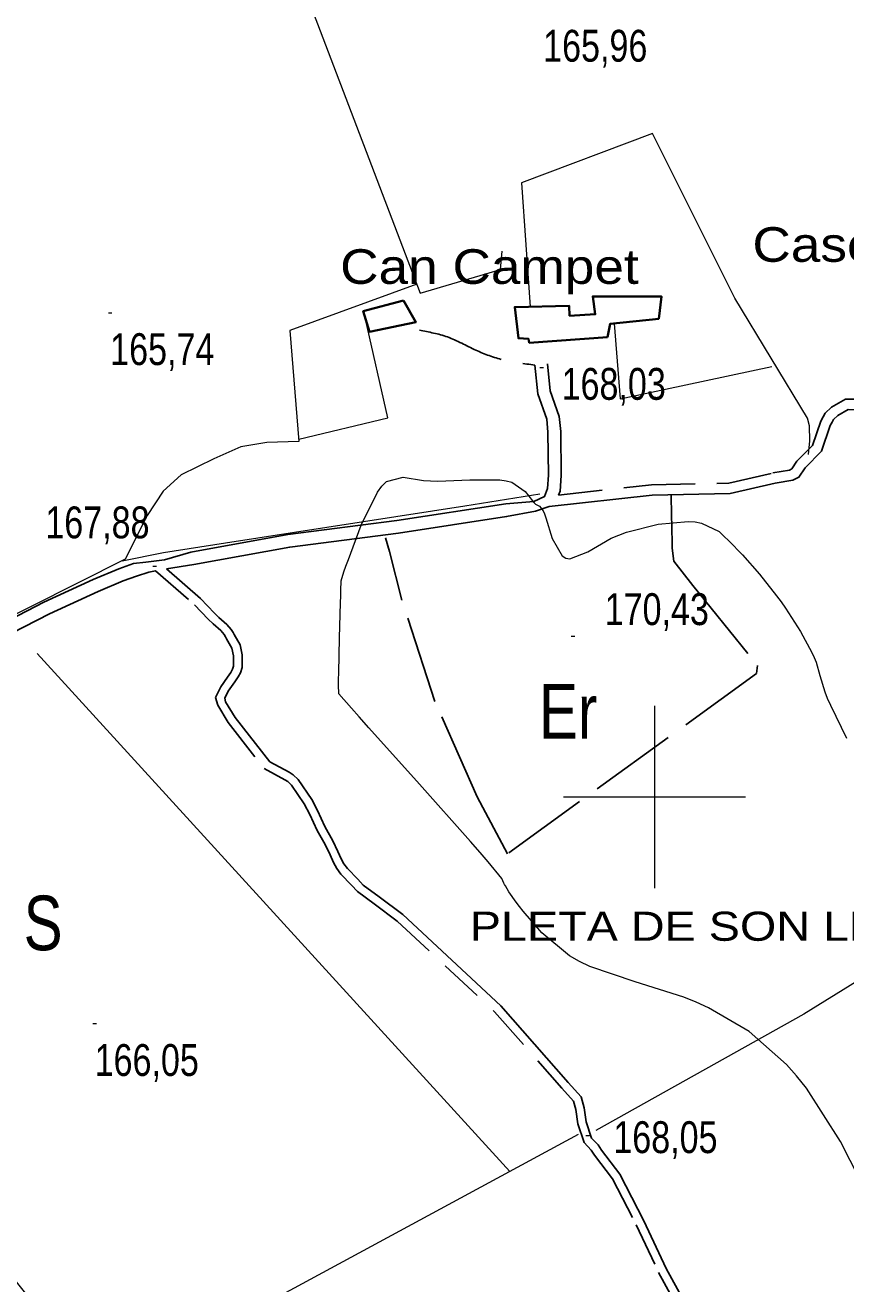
# Model space of a CAD drawing. Extents: x -807245 to 6129983, y -54972206 to 262146364.
# Drawn here: x 490827.1 to 491052.5, y 4382866.3 to 4383212 of the extents above; entities that cross this region are included whole.
import ezdxf
from ezdxf.enums import TextEntityAlignment as Align

# ---------------------------------------------------------------- set-up
doc = ezdxf.new("R2010")
doc.units = 0
doc.header["$LTSCALE"] = 4
doc.linetypes.add('LONG_DASHED', pattern=[7.5, 6, -1.5])
doc.linetypes.add('MEDIUM_DASHED', pattern=[4.5, 3, -1.5])
for name, color, linetype, lineweight in [('1', 7, 'Continuous', 13), ('25', 7, 'LONG_DASHED', 25), ('27', 7, 'Continuous', 25), ('38', 7, 'Continuous', 25), ('47', 7, 'Continuous', 35), ('51', 7, 'Continuous', 13), ('7', 7, 'Continuous', 13), ('9', 7, 'Continuous', 13)]:
    doc.layers.add(name, color=color, linetype=linetype, lineweight=lineweight)
doc.layers.add('31', color=7, linetype='Continuous')
doc.layers.add('5', color=7, linetype='Continuous')

msp = doc.modelspace()

# ---------------------------------------------------------------- linework, layer by layer
at = {"layer": '1'}
for p, q in [((491000, 4383025), (491000, 4382975)), ((490975, 4383000), (491025, 4383000))]:
    msp.add_line(p, q, dxfattribs=at)
at = {"layer": '25'}
msp.add_lwpolyline([(491004.6, 4383082.96), (491004.66, 4383077.34), (491004.73, 4383074.41), (491004.73, 4383074.04), (491004.79, 4383069.62), (491004.86, 4383068.34), (491005.3, 4383064.74), (491010.53, 4383058.05), (491028.23, 4383036.1), (491028, 4383033.93), (490959.62, 4382984.43), (490951.27, 4383000.05), (490939.65, 4383026.25), (490930.59, 4383054.09), (490927.18, 4383067.38), (490926.06, 4383071.13)], dxfattribs=at)
at = {"layer": '27'}
msp.add_spline([(491255.21, 4383970.03), (491244.34, 4383967.52), (491230.36, 4383957.66), (491230.81, 4383957.81), (491230.81, 4383957.81), (491220.15, 4383951.47), (491212.7, 4383943.01), (491205.06, 4383944.23), (491184.85, 4383957.71), (491152.82, 4383981.27), (491128.36, 4384004.58), (491128.29, 4384004.88), (491122.26, 4384021.39), (491095.75, 4384034.59), (491071.07, 4384059.32), (491064.71, 4384065.12)], degree=3, dxfattribs=at)
at = {"layer": '38'}
for points in [[(490811.19, 4383042.65), (490832.26, 4383053.49), (490845.75, 4383059.69), (490852.79, 4383062.62), (490856.89, 4383064.09), (490860.26, 4383064.48), (490865.39, 4383065.16), (490872.63, 4383067.26), (490899.23, 4383072.07), (490929.17, 4383075.97), (490959.14, 4383080.54), (490966.81, 4383081.13), (490969.77, 4383082.56), (490970.6, 4383084.71), (490970.82, 4383088.42), (490970.71, 4383100.16), (490970.36, 4383103.75), (490967.91, 4383110.73), (490967.1, 4383118.61)], [(490973.65, 4383082.9), (490974.06, 4383083.96), (490974.32, 4383088.33), (490974.21, 4383100.34), (490973.81, 4383104.51), (490971.36, 4383111.5), (490970.58, 4383118.98)], [(490971.07, 4383079.75), (490999.33, 4383082.88), (491020.73, 4383083.34), (491033.09, 4383086.18), (491037.94, 4383087.02), (491039.65, 4383087.87), (491041.32, 4383090.44), (491045.84, 4383094.94), (491048.26, 4383102.05), (491048.78, 4383102.95), (491049.18, 4383103.65), (491050.36, 4383104.81), (491053.2, 4383106.4), (491062.68, 4383106.37), (491079.69, 4383105.79), (491090.52, 4383105.69), (491093.97, 4383105.68), (491094.81, 4383105.67), (491098.25, 4383106.04), (491103.6, 4383110.06)], [(490865.9, 4383062.64), (490873.45, 4383063.85), (490899.77, 4383068.61), (490929.66, 4383072.5), (490959.36, 4383077.03), (490967.25, 4383078.5), (490971.07, 4383079.75)], [(490865.9, 4383062.64), (490875.26, 4383054.51), (490879.09, 4383050.51), (490880.33, 4383049.26), (490882.52, 4383047.36), (490883.72, 4383045.99), (490884.21, 4383045.17), (490884.51, 4383044.63), (490886.14, 4383041.75), (490886.69, 4383039.01), (490886.69, 4383037.88), (490886.68, 4383035.6), (490886.25, 4383034.14), (490885.59, 4383032.99), (490884.66, 4383031.61), (490882.89, 4383029.03), (490881.91, 4383027.1), (490882.17, 4383026.14), (490884.78, 4383021.83), (490894.29, 4383009.67), (490899.64, 4383006.79), (490900.69, 4383006.13), (490902.08, 4383004.82), (490905.81, 4382999.3), (490907.41, 4382996.25), (490909.41, 4382991.9), (490911.65, 4382988), (490913.01, 4382985.03), (490913.88, 4382983.03), (490914.66, 4382981.68), (490915.66, 4382980.34), (490918.46, 4382977.43), (490919.99, 4382975.82), (490924.35, 4382972.55), (490930.81, 4382967.71), (490957.72, 4382942.67), (490976.27, 4382921.6), (490979.83, 4382917.64), (490980.7, 4382914.64), (490981.21, 4382910.75), (490982.7, 4382906.33), (490984.5, 4382904.44), (490985.42, 4382902.99), (490990.44, 4382896.42), (490997.04, 4382883.58), (491003.22, 4382870.53), (491013.1, 4382852.48)], [(490709.37, 4382956.35), (490722.41, 4382965.9), (490724.86, 4382968.74), (490726.52, 4382970.89), (490728.35, 4382974.53), (490729.62, 4382978.74), (490733.25, 4382984.93), (490736.44, 4382990.04), (490739.55, 4382993.28), (490744.18, 4382997.58), (490749.81, 4383001.94), (490765.95, 4383012.18), (490780.69, 4383021.17), (490792.17, 4383027.65), (490812.86, 4383039.57), (490833.8, 4383050.34), (490847.16, 4383056.48), (490854.06, 4383059.35), (490857.69, 4383060.66), (490861.03, 4383061.73), (490862.93, 4383062.09)]]:
    msp.add_lwpolyline(points, dxfattribs=at)
at = {"layer": '38', "linetype": 'MEDIUM_DASHED'}
for points in [[(490973.65, 4383082.9), (490999.14, 4383085.73), (491020.37, 4383086.18), (491032.52, 4383088.98), (491037.05, 4383089.76), (491037.68, 4383090.08), (491039.09, 4383092.25), (491043.35, 4383096.49), (491045.65, 4383103.24), (491046.31, 4383104.38), (491046.9, 4383105.41), (491048.62, 4383107.1), (491052.45, 4383109.26), (491062.73, 4383109.23), (491079.75, 4383108.65), (491090.54, 4383108.55), (491093.99, 4383108.54), (491094.68, 4383108.53), (491097.16, 4383108.79), (491101.88, 4383112.34)], [(490862.93, 4383062.09), (490873.63, 4383052.8), (490877.4, 4383048.87), (490878.72, 4383047.53), (490880.85, 4383045.69), (490881.8, 4383044.6), (490882.16, 4383044), (490882.44, 4383043.48), (490883.9, 4383040.91), (490884.33, 4383038.77), (490884.33, 4383037.88), (490884.32, 4383035.95), (490884.06, 4383035.07), (490883.58, 4383034.23), (490882.71, 4383032.94), (490880.85, 4383030.24), (490879.39, 4383027.35), (490879.98, 4383025.19), (490882.83, 4383020.48), (490892.74, 4383007.82), (490898.45, 4383004.75), (490899.24, 4383004.25), (490900.27, 4383003.28), (490903.78, 4382998.09), (490905.29, 4382995.21), (490907.31, 4382990.82), (490909.55, 4382986.92), (490910.85, 4382984.07), (490911.77, 4382981.97), (490912.68, 4382980.39), (490913.85, 4382978.81), (490916.76, 4382975.79), (490918.41, 4382974.05), (490922.93, 4382970.66), (490929.29, 4382965.89), (490956.02, 4382941.03), (490974.51, 4382920.03), (490977.71, 4382916.46), (490978.38, 4382914.15), (490978.9, 4382910.22), (490980.63, 4382905.09), (490982.62, 4382902.98), (490983.48, 4382901.64), (490988.43, 4382895.15), (490994.92, 4382882.53), (491001.12, 4382869.45), (491011.09, 4382851.24)]]:
    msp.add_lwpolyline(points, dxfattribs=at)
at = {"layer": '38', "linetype": 'LONG_DASHED'}
msp.add_spline([(490935.38, 4383128.16), (490943.1, 4383126.34), (490950.89, 4383122.71), (490958.38, 4383120.07), (490967.1, 4383118.61)], degree=3, dxfattribs=at)
at = {"layer": '47'}
for points in [[(490930.99, 4383136.35), (490919.95, 4383133.38), (490921.66, 4383127.75), (490934.41, 4383130.36)], [(490987.11, 4383126.28), (490965.59, 4383124.77), (490965.37, 4383125.82), (490962.6, 4383125.98), (490961.57, 4383134.53), (490976.57, 4383134.86), (490976.64, 4383132.16), (490983.68, 4383132.59), (490983.02, 4383137.46), (491001.92, 4383137.41), (491001.15, 4383131.34), (490987.8, 4383129.95)]]:
    msp.add_lwpolyline(points, close=True, dxfattribs=at)
at = {"layer": '51'}
msp.add_line((490960.2, 4382897.14), (490830.37, 4383039.4), dxfattribs=at)
for points in [[(490804.59, 4383480.92), (490854.18, 4383351.92), (490935.64, 4383138.36), (490957.63, 4383144.89), (490958.09, 4383149.91)], [(491042.28, 4383094.1), (491042.66, 4383097.77), (491042.6, 4383101.97), (491042.01, 4383104.07), (491022.01, 4383136.97), (490999.43, 4383182.18), (490963.47, 4383168.71), (490965.79, 4383134.62)], [(490934.69, 4383140.87), (490899.77, 4383128.12), (490902.3, 4383097.59), (490893.45, 4383097.39), (490886.33, 4383096.14), (490878.97, 4383092.86), (490869.96, 4383088.47), (490864.99, 4383083.98), (490860.63, 4383077.32), (490854.59, 4383065.27), (490789.41, 4383032.55)], [(490902.24, 4383098.3), (490926.69, 4383104.12), (490920.62, 4383131.2)], [(490988.86, 4383130.07), (490990.51, 4383109.32), (491032.23, 4383118.19)], [(490853.73, 4383064.84), (490865.09, 4383067.11), (490882.12, 4383069.76), (490947.84, 4383079.99), (490968.47, 4383083.3)], [(490720.29, 4382963.03), (490736.16, 4382977.45), (490848.58, 4382836.83), (490979.11, 4382907.36)], [(491099.63, 4382976.59), (491040.99, 4382940.32), (490983.83, 4382908.4)]]:
    msp.add_lwpolyline(points, dxfattribs=at)
at = {"layer": '7'}
for p, q in [((490849.95, 4383132.99), (490850.95, 4383132.99)), ((490968.44, 4383117.94), (490969.44, 4383117.94)), ((490862.18, 4383063.37), (490863.18, 4383063.37)), ((490977.07, 4383044.13), (490978.07, 4383044.13)), ((490845.68, 4382937.76), (490846.68, 4382937.76)), ((490981.15, 4382907.05), (490982.15, 4382907.05))]:
    msp.add_line(p, q, dxfattribs=at)
at = {"layer": '9'}
for points in [[(491059.04, 4382889.77), (491051.08, 4382905.36), (491041.71, 4382920.01), (491039.02, 4382923.42), (491036.28, 4382926.56), (491026.01, 4382935.59), (491014.78, 4382942.09), (491011.44, 4382943.63), (491007.99, 4382945.05), (490994.67, 4382949.28), (490982.23, 4382953.46), (490979.33, 4382954.86), (490976.67, 4382956.36), (490969.03, 4382962.67), (490963.93, 4382968.65), (490962.86, 4382969.95), (490961.95, 4382971.09), (490959.93, 4382973.92), (490959.01, 4382975.58), (490958.8, 4382975.99), (490958.6, 4382976.37), (490958.04, 4382977.57), (490954.3, 4382982.18), (490952.1, 4382984.71), (490949.4, 4382987.8), (490935.42, 4383003.48), (490921.52, 4383018.99), (490918.85, 4383021.97), (490916.7, 4383024.37), (490913.22, 4383028.29), (490913.18, 4383030.77), (490913.21, 4383032.26), (490913.24, 4383034.11), (490913.49, 4383043.72), (490913.75, 4383053.35), (490913.8, 4383055.22), (490913.83, 4383056.73), (490913.86, 4383059.33), (490914.68, 4383061.87), (490915.22, 4383063.36), (490915.88, 4383065.19), (490919.41, 4383074.63), (490923.85, 4383083.75), (490925.09, 4383085.37), (490926.34, 4383086.61), (490930.91, 4383087.83), (490936.52, 4383086.92), (490938.42, 4383086.81), (490940.49, 4383086.76), (490949.21, 4383087.13), (490957.47, 4383087.11), (490959.24, 4383086.83), (490960.78, 4383086.42), (490964.49, 4383083.94), (490966.45, 4383081.32), (490966.89, 4383080.83), (490967.29, 4383080.44)], [(490967.29, 4383080.44), (490968.36, 4383079.88), (490969.39, 4383078.58), (490969.75, 4383077.73), (490970.16, 4383076.67), (490971.9, 4383071.03), (490974.61, 4383066.19), (490975.61, 4383065.63), (490976.73, 4383065.4), (490981.69, 4383067.37), (490988.11, 4383071.06), (490990.14, 4383071.92), (490992.29, 4383072.7), (491000.97, 4383074.93), (491009.27, 4383075.69), (491011.18, 4383075.54), (491012.91, 4383075.24), (491017.76, 4383072.88), (491021.72, 4383069.04), (491022.9, 4383067.81), (491024.12, 4383066.5), (491028.81, 4383061.18), (491033.53, 4383055.25), (491034.77, 4383053.56), (491035.97, 4383051.85), (491040.05, 4383045.48), (491043.23, 4383039.67), (491043.86, 4383038.3), (491044.39, 4383037.04), (491045.41, 4383033.36), (491046.73, 4383028.91), (491047.45, 4383027.16), (491048.32, 4383025.19), (491052.74, 4383016.2)]]:
    msp.add_lwpolyline(points, dxfattribs=at)

# ---------------------------------------------------------------- texts
at = {"layer": '31', "width": 0.8}
for s, p in [('Er', (490976.26, 4383016.02)), ('S', (490832.03, 4382957.91))]:
    msp.add_text(s, height=15, dxfattribs=at).set_placement(p, align=Align.CENTER)
at = {"layer": '5'}
for s, height, width, p in [('Caseta d\'en Ti" Brau', 9.5, 1.15, (491160.72, 4383146.98)), ('Can Campet', 9.5, 1.15, (490995.64, 4383140.92)), ('PLETA DE SON LLUBINET', 8, 1.2, (491107.62, 4382960.51))]:
    msp.add_text(s, height=height, dxfattribs=dict(at, width=width)).set_placement(p, align=Align.RIGHT)
at = {"layer": '7', "width": 0.8}
for s, p in [('165,96', (490969.39, 4383201.94)), ('165,74', (490850.45, 4383118.62)), ('168,03', (490974.45, 4383109.08)), ('167,88', (490832.63, 4383071.04)), ('170,43', (490986.29, 4383047.21)), ('166,05', (490846.18, 4382923.39)), ('168,05', (490988.66, 4382902.2))]:
    msp.add_text(s, height=8.75, dxfattribs=at).set_placement(p)

doc.saveas('drawing.dxf')
